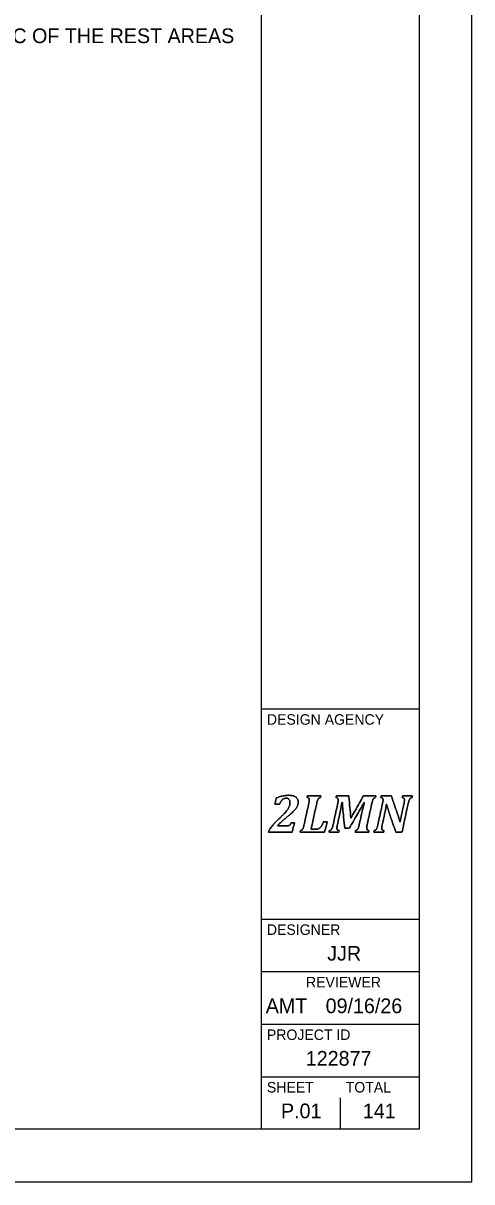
# Model space of a CAD drawing. Extents: x 0 to 34, y 0 to 22.
# Drawn here: x 29.73 to 34, y 0 to 11.03 of the extents above; entities that cross this region are included whole.
import ezdxf

# ---------------------------------------------------------------- set-up
doc = ezdxf.new("R2010")
doc.units = 0
for name, color, linetype in [('SH_Border', 7, 'Continuous'), ('SH_Cut_Line', 7, 'Continuous'), ('SH_Data', 7, 'Continuous')]:
    doc.layers.add(name, color=color, linetype=linetype)

msp = doc.modelspace()

# ---------------------------------------------------------------- linework, layer by layer
at = {"layer": 'SH_Border'}
for p, q in [((32, 0.5), (32, 21.5)), ((32, 4.5), (33.5, 4.5)), ((32, 2.5), (33.5, 2.5)), ((32, 2), (33.5, 2)), ((32, 1.5), (33.5, 1.5)), ((32, 1), (33.5, 1))]:
    msp.add_line(p, q, dxfattribs=at)
msp.add_lwpolyline([(1.5, 21.5), (33.5, 21.5), (33.5, 0.5), (1.5, 0.5)], close=True, dxfattribs=at)
at = {"layer": 'SH_Cut_Line'}
msp.add_lwpolyline([(0, 0), (34, 0), (34, 22), (0, 22)], close=True, dxfattribs=at)
at = {"layer": 'SH_Data'}
for p, q in [((32.75, 3.5), (32.75, 3.5)), ((32.75, 0.5), (32.75, 0.8)), ((32.375, 0.675), (32.375, 0.675))]:
    msp.add_line(p, q, dxfattribs=at)
for points in [[(32.237, 3.388), (32.246, 3.388), (32.253, 3.389), (32.258, 3.39), (32.263, 3.392), (32.267, 3.394), (32.27, 3.397), (32.273, 3.401), (32.277, 3.408), (32.281, 3.417), (32.281, 3.417), (32.312, 3.417), (32.312, 3.417), (32.312, 3.417), (32.29, 3.326), (32.29, 3.326), (32.29, 3.326), (32.066, 3.326), (32.066, 3.326), (32.066, 3.326), (32.069, 3.343), (32.069, 3.343), (32.078, 3.358), (32.091, 3.375), (32.106, 3.394), (32.122, 3.412), (32.144, 3.435), (32.172, 3.462), (32.197, 3.486), (32.217, 3.506), (32.23, 3.521), (32.243, 3.537), (32.253, 3.551), (32.259, 3.566), (32.266, 3.58), (32.269, 3.595), (32.269, 3.61), (32.269, 3.622), (32.266, 3.632), (32.26, 3.64), (32.253, 3.647), (32.245, 3.65), (32.234, 3.65), (32.22, 3.65), (32.208, 3.646), (32.198, 3.636), (32.188, 3.627), (32.18, 3.613), (32.172, 3.593), (32.172, 3.593), (32.126, 3.593), (32.126, 3.593), (32.126, 3.593), (32.14, 3.654), (32.14, 3.654), (32.166, 3.663), (32.188, 3.669), (32.205, 3.673), (32.223, 3.676), (32.24, 3.678), (32.258, 3.678), (32.278, 3.678), (32.295, 3.675), (32.309, 3.669), (32.322, 3.664), (32.332, 3.656), (32.339, 3.646), (32.345, 3.637), (32.348, 3.626), (32.348, 3.613), (32.348, 3.602), (32.346, 3.591), (32.342, 3.581), (32.339, 3.571), (32.333, 3.56), (32.324, 3.549), (32.315, 3.539), (32.304, 3.526), (32.289, 3.513), (32.275, 3.499), (32.254, 3.482), (32.228, 3.46), (32.216, 3.45), (32.202, 3.438), (32.188, 3.425), (32.174, 3.412), (32.162, 3.4), (32.154, 3.391), (32.154, 3.391), (32.153, 3.388), (32.153, 3.388), (32.153, 3.388), (32.237, 3.388), (32.237, 3.388)], [(32.237, 3.388), (32.237, 3.388), (32.153, 3.388), (32.153, 3.388), (32.153, 3.388), (32.154, 3.391), (32.154, 3.391), (32.162, 3.4), (32.174, 3.412), (32.188, 3.425), (32.202, 3.438), (32.216, 3.45), (32.228, 3.46), (32.254, 3.482), (32.275, 3.499), (32.289, 3.513), (32.304, 3.526), (32.315, 3.539), (32.324, 3.549), (32.333, 3.56), (32.339, 3.571), (32.342, 3.581), (32.346, 3.591), (32.348, 3.602), (32.348, 3.613), (32.348, 3.626), (32.345, 3.637), (32.339, 3.646), (32.332, 3.656), (32.322, 3.664), (32.309, 3.669), (32.295, 3.675), (32.278, 3.678), (32.258, 3.678), (32.24, 3.678), (32.223, 3.676), (32.205, 3.673), (32.188, 3.669), (32.166, 3.663), (32.14, 3.654), (32.14, 3.654), (32.126, 3.593), (32.126, 3.593), (32.126, 3.593), (32.172, 3.593), (32.172, 3.593), (32.18, 3.613), (32.188, 3.627), (32.198, 3.636), (32.208, 3.646), (32.22, 3.65), (32.234, 3.65), (32.245, 3.65), (32.253, 3.647), (32.26, 3.64), (32.266, 3.632), (32.269, 3.622), (32.269, 3.61), (32.269, 3.595), (32.266, 3.58), (32.259, 3.566), (32.253, 3.551), (32.243, 3.537), (32.23, 3.521), (32.217, 3.506), (32.197, 3.486), (32.172, 3.462), (32.144, 3.435), (32.122, 3.412), (32.106, 3.394), (32.091, 3.375), (32.078, 3.358), (32.069, 3.343), (32.069, 3.343), (32.066, 3.326), (32.066, 3.326), (32.066, 3.326), (32.29, 3.326), (32.29, 3.326), (32.29, 3.326), (32.312, 3.417), (32.312, 3.417), (32.312, 3.417), (32.281, 3.417), (32.281, 3.417), (32.277, 3.408), (32.273, 3.401), (32.27, 3.397), (32.267, 3.394), (32.263, 3.392), (32.258, 3.39), (32.253, 3.389), (32.246, 3.388), (32.237, 3.388)], [(32.518, 3.356), (32.527, 3.356), (32.533, 3.357), (32.538, 3.358), (32.542, 3.36), (32.546, 3.362), (32.55, 3.365), (32.554, 3.368), (32.558, 3.372), (32.562, 3.377), (32.567, 3.382), (32.571, 3.388), (32.576, 3.397), (32.58, 3.405), (32.585, 3.415), (32.589, 3.427), (32.589, 3.427), (32.624, 3.427), (32.624, 3.427), (32.624, 3.427), (32.598, 3.326), (32.598, 3.326), (32.598, 3.326), (32.365, 3.326), (32.365, 3.326), (32.365, 3.326), (32.369, 3.343), (32.369, 3.343), (32.376, 3.345), (32.381, 3.348), (32.385, 3.351), (32.389, 3.355), (32.392, 3.36), (32.395, 3.366), (32.398, 3.373), (32.4, 3.382), (32.403, 3.395), (32.403, 3.395), (32.449, 3.605), (32.449, 3.605), (32.452, 3.615), (32.453, 3.625), (32.453, 3.635), (32.453, 3.642), (32.451, 3.647), (32.448, 3.651), (32.444, 3.654), (32.439, 3.656), (32.432, 3.657), (32.432, 3.657), (32.435, 3.674), (32.435, 3.674), (32.435, 3.674), (32.563, 3.674), (32.563, 3.674), (32.563, 3.674), (32.559, 3.657), (32.559, 3.657), (32.552, 3.655), (32.547, 3.652), (32.543, 3.649), (32.539, 3.645), (32.536, 3.64), (32.533, 3.634), (32.531, 3.627), (32.528, 3.618), (32.525, 3.605), (32.525, 3.605), (32.47, 3.356), (32.47, 3.356), (32.47, 3.356), (32.518, 3.356), (32.518, 3.356)], [(32.518, 3.356), (32.518, 3.356), (32.47, 3.356), (32.47, 3.356), (32.47, 3.356), (32.525, 3.605), (32.525, 3.605), (32.528, 3.618), (32.531, 3.627), (32.533, 3.634), (32.536, 3.64), (32.539, 3.645), (32.543, 3.649), (32.547, 3.652), (32.552, 3.655), (32.559, 3.657), (32.559, 3.657), (32.563, 3.674), (32.563, 3.674), (32.563, 3.674), (32.435, 3.674), (32.435, 3.674), (32.435, 3.674), (32.432, 3.657), (32.432, 3.657), (32.439, 3.656), (32.444, 3.654), (32.448, 3.651), (32.451, 3.647), (32.453, 3.642), (32.453, 3.635), (32.453, 3.625), (32.452, 3.615), (32.449, 3.605), (32.449, 3.605), (32.403, 3.395), (32.403, 3.395), (32.4, 3.382), (32.398, 3.373), (32.395, 3.366), (32.392, 3.36), (32.389, 3.355), (32.385, 3.351), (32.381, 3.348), (32.376, 3.345), (32.369, 3.343), (32.369, 3.343), (32.365, 3.326), (32.365, 3.326), (32.365, 3.326), (32.598, 3.326), (32.598, 3.326), (32.598, 3.326), (32.624, 3.427), (32.624, 3.427), (32.624, 3.427), (32.589, 3.427), (32.589, 3.427), (32.585, 3.415), (32.58, 3.405), (32.576, 3.397), (32.571, 3.388), (32.567, 3.382), (32.562, 3.377), (32.558, 3.372), (32.554, 3.368), (32.55, 3.365), (32.546, 3.362), (32.542, 3.36), (32.538, 3.358), (32.533, 3.357), (32.527, 3.356), (32.518, 3.356)], [(32.829, 3.674), (32.829, 3.674), (32.849, 3.461), (32.849, 3.461), (32.849, 3.461), (32.969, 3.674), (32.969, 3.674), (32.969, 3.674), (33.087, 3.674), (33.087, 3.674), (33.087, 3.674), (33.084, 3.657), (33.084, 3.657), (33.077, 3.655), (33.071, 3.652), (33.067, 3.649), (33.064, 3.645), (33.06, 3.64), (33.058, 3.634), (33.055, 3.627), (33.052, 3.618), (33.05, 3.605), (33.05, 3.605), (33.003, 3.395), (33.003, 3.395), (33.002, 3.39), (33.002, 3.387), (33.001, 3.384), (33.001, 3.382), (33.001, 3.379), (33, 3.376), (33, 3.373), (33, 3.369), (33, 3.365), (33, 3.358), (33.002, 3.353), (33.005, 3.349), (33.008, 3.346), (33.014, 3.344), (33.021, 3.343), (33.021, 3.343), (33.018, 3.326), (33.018, 3.326), (33.018, 3.326), (32.89, 3.326), (32.89, 3.326), (32.89, 3.326), (32.893, 3.343), (32.893, 3.343), (32.9, 3.345), (32.906, 3.348), (32.91, 3.351), (32.914, 3.355), (32.917, 3.36), (32.919, 3.366), (32.922, 3.373), (32.925, 3.382), (32.928, 3.395), (32.928, 3.395), (32.951, 3.502), (32.951, 3.502), (32.954, 3.513), (32.957, 3.529), (32.962, 3.548), (32.967, 3.568), (32.972, 3.588), (32.978, 3.609), (32.978, 3.609), (32.973, 3.609), (32.973, 3.609), (32.965, 3.594), (32.957, 3.579), (32.948, 3.563), (32.948, 3.563), (32.833, 3.364), (32.833, 3.364), (32.833, 3.364), (32.792, 3.364), (32.792, 3.364), (32.792, 3.364), (32.775, 3.518), (32.775, 3.518), (32.773, 3.537), (32.772, 3.554), (32.77, 3.569), (32.769, 3.583), (32.768, 3.597), (32.768, 3.611), (32.768, 3.611), (32.764, 3.611), (32.764, 3.611), (32.761, 3.596), (32.758, 3.578), (32.755, 3.558), (32.751, 3.538), (32.747, 3.521), (32.744, 3.507), (32.744, 3.507), (32.72, 3.395), (32.72, 3.395), (32.719, 3.39), (32.718, 3.387), (32.718, 3.384), (32.717, 3.382), (32.717, 3.379), (32.717, 3.376), (32.717, 3.373), (32.716, 3.369), (32.716, 3.365), (32.716, 3.358), (32.718, 3.353), (32.721, 3.349), (32.725, 3.346), (32.73, 3.344), (32.738, 3.343), (32.738, 3.343), (32.734, 3.326), (32.734, 3.326), (32.734, 3.326), (32.641, 3.326), (32.641, 3.326), (32.641, 3.326), (32.644, 3.343), (32.644, 3.343), (32.651, 3.345), (32.657, 3.348), (32.661, 3.351), (32.665, 3.355), (32.668, 3.36), (32.67, 3.366), (32.673, 3.373), (32.676, 3.382), (32.679, 3.395), (32.679, 3.395), (32.725, 3.605), (32.725, 3.605), (32.727, 3.615), (32.728, 3.625), (32.728, 3.635), (32.728, 3.642), (32.727, 3.647), (32.723, 3.651), (32.72, 3.654), (32.715, 3.656), (32.707, 3.657), (32.707, 3.657), (32.711, 3.674), (32.711, 3.674), (32.711, 3.674), (32.829, 3.674), (32.829, 3.674)], [(32.829, 3.674), (32.829, 3.674), (32.711, 3.674), (32.711, 3.674), (32.711, 3.674), (32.707, 3.657), (32.707, 3.657), (32.715, 3.656), (32.72, 3.654), (32.723, 3.651), (32.727, 3.647), (32.728, 3.642), (32.728, 3.635), (32.728, 3.625), (32.727, 3.615), (32.725, 3.605), (32.725, 3.605), (32.679, 3.395), (32.679, 3.395), (32.676, 3.382), (32.673, 3.373), (32.67, 3.366), (32.668, 3.36), (32.665, 3.355), (32.661, 3.351), (32.657, 3.348), (32.651, 3.345), (32.644, 3.343), (32.644, 3.343), (32.641, 3.326), (32.641, 3.326), (32.641, 3.326), (32.734, 3.326), (32.734, 3.326), (32.734, 3.326), (32.738, 3.343), (32.738, 3.343), (32.73, 3.344), (32.725, 3.346), (32.721, 3.349), (32.718, 3.353), (32.716, 3.358), (32.716, 3.365), (32.716, 3.369), (32.717, 3.373), (32.717, 3.376), (32.717, 3.379), (32.717, 3.382), (32.718, 3.384), (32.718, 3.387), (32.719, 3.39), (32.72, 3.395), (32.72, 3.395), (32.744, 3.507), (32.744, 3.507), (32.747, 3.521), (32.751, 3.538), (32.755, 3.558), (32.758, 3.578), (32.761, 3.596), (32.764, 3.611), (32.764, 3.611), (32.768, 3.611), (32.768, 3.611), (32.768, 3.597), (32.769, 3.583), (32.77, 3.569), (32.772, 3.554), (32.773, 3.537), (32.775, 3.518), (32.775, 3.518), (32.792, 3.364), (32.792, 3.364), (32.792, 3.364), (32.833, 3.364), (32.833, 3.364), (32.833, 3.364), (32.948, 3.563), (32.948, 3.563), (32.957, 3.579), (32.965, 3.594), (32.973, 3.609), (32.973, 3.609), (32.978, 3.609), (32.978, 3.609), (32.972, 3.588), (32.967, 3.568), (32.962, 3.548), (32.957, 3.529), (32.954, 3.513), (32.951, 3.502), (32.951, 3.502), (32.928, 3.395), (32.928, 3.395), (32.925, 3.382), (32.922, 3.373), (32.919, 3.366), (32.917, 3.36), (32.914, 3.355), (32.91, 3.351), (32.906, 3.348), (32.9, 3.345), (32.893, 3.343), (32.893, 3.343), (32.89, 3.326), (32.89, 3.326), (32.89, 3.326), (33.018, 3.326), (33.018, 3.326), (33.018, 3.326), (33.021, 3.343), (33.021, 3.343), (33.014, 3.344), (33.008, 3.346), (33.005, 3.349), (33.002, 3.353), (33, 3.358), (33, 3.365), (33, 3.369), (33, 3.373), (33, 3.376), (33.001, 3.379), (33.001, 3.382), (33.001, 3.384), (33.002, 3.387), (33.002, 3.39), (33.003, 3.395), (33.003, 3.395), (33.05, 3.605), (33.05, 3.605), (33.052, 3.618), (33.055, 3.627), (33.058, 3.634), (33.06, 3.64), (33.064, 3.645), (33.067, 3.649), (33.071, 3.652), (33.077, 3.655), (33.084, 3.657), (33.084, 3.657), (33.087, 3.674), (33.087, 3.674), (33.087, 3.674), (32.969, 3.674), (32.969, 3.674), (32.969, 3.674), (32.849, 3.461), (32.849, 3.461), (32.849, 3.461), (32.829, 3.674), (32.829, 3.674)], [(33.137, 3.674), (33.137, 3.674), (33.234, 3.674), (33.234, 3.674), (33.234, 3.674), (33.283, 3.53), (33.283, 3.53), (33.296, 3.49), (33.307, 3.456), (33.315, 3.426), (33.315, 3.426), (33.318, 3.426), (33.318, 3.426), (33.323, 3.455), (33.329, 3.488), (33.337, 3.523), (33.337, 3.523), (33.355, 3.605), (33.355, 3.605), (33.357, 3.615), (33.358, 3.625), (33.358, 3.635), (33.358, 3.642), (33.357, 3.647), (33.353, 3.651), (33.35, 3.654), (33.345, 3.656), (33.337, 3.657), (33.337, 3.657), (33.341, 3.674), (33.341, 3.674), (33.341, 3.674), (33.434, 3.674), (33.434, 3.674), (33.434, 3.674), (33.431, 3.657), (33.431, 3.657), (33.424, 3.655), (33.418, 3.652), (33.414, 3.649), (33.41, 3.645), (33.407, 3.64), (33.405, 3.634), (33.402, 3.627), (33.399, 3.618), (33.396, 3.605), (33.396, 3.605), (33.335, 3.326), (33.335, 3.326), (33.335, 3.326), (33.277, 3.326), (33.277, 3.326), (33.277, 3.326), (33.216, 3.504), (33.216, 3.504), (33.211, 3.518), (33.207, 3.531), (33.204, 3.543), (33.2, 3.556), (33.195, 3.571), (33.19, 3.59), (33.19, 3.59), (33.186, 3.59), (33.186, 3.59), (33.185, 3.579), (33.182, 3.563), (33.179, 3.543), (33.175, 3.523), (33.17, 3.501), (33.165, 3.478), (33.165, 3.478), (33.147, 3.395), (33.147, 3.395), (33.146, 3.39), (33.145, 3.387), (33.145, 3.384), (33.144, 3.382), (33.144, 3.379), (33.144, 3.376), (33.143, 3.373), (33.143, 3.369), (33.143, 3.365), (33.143, 3.358), (33.145, 3.353), (33.148, 3.349), (33.152, 3.346), (33.157, 3.344), (33.164, 3.343), (33.164, 3.343), (33.161, 3.326), (33.161, 3.326), (33.161, 3.326), (33.067, 3.326), (33.067, 3.326), (33.067, 3.326), (33.071, 3.343), (33.071, 3.343), (33.078, 3.345), (33.083, 3.348), (33.087, 3.351), (33.091, 3.355), (33.094, 3.36), (33.097, 3.366), (33.1, 3.373), (33.102, 3.382), (33.105, 3.395), (33.105, 3.395), (33.151, 3.605), (33.151, 3.605), (33.154, 3.615), (33.155, 3.625), (33.155, 3.635), (33.155, 3.642), (33.153, 3.647), (33.15, 3.651), (33.146, 3.654), (33.141, 3.656), (33.134, 3.657), (33.134, 3.657), (33.137, 3.674), (33.137, 3.674)], [(33.137, 3.674), (33.137, 3.674), (33.134, 3.657), (33.134, 3.657), (33.141, 3.656), (33.146, 3.654), (33.15, 3.651), (33.153, 3.647), (33.155, 3.642), (33.155, 3.635), (33.155, 3.625), (33.154, 3.615), (33.151, 3.605), (33.151, 3.605), (33.105, 3.395), (33.105, 3.395), (33.102, 3.382), (33.1, 3.373), (33.097, 3.366), (33.094, 3.36), (33.091, 3.355), (33.087, 3.351), (33.083, 3.348), (33.078, 3.345), (33.071, 3.343), (33.071, 3.343), (33.067, 3.326), (33.067, 3.326), (33.067, 3.326), (33.161, 3.326), (33.161, 3.326), (33.161, 3.326), (33.164, 3.343), (33.164, 3.343), (33.157, 3.344), (33.152, 3.346), (33.148, 3.349), (33.145, 3.353), (33.143, 3.358), (33.143, 3.365), (33.143, 3.369), (33.143, 3.373), (33.144, 3.376), (33.144, 3.379), (33.144, 3.382), (33.145, 3.384), (33.145, 3.387), (33.146, 3.39), (33.147, 3.395), (33.147, 3.395), (33.165, 3.478), (33.165, 3.478), (33.17, 3.501), (33.175, 3.523), (33.179, 3.543), (33.182, 3.563), (33.185, 3.579), (33.186, 3.59), (33.186, 3.59), (33.19, 3.59), (33.19, 3.59), (33.195, 3.571), (33.2, 3.556), (33.204, 3.543), (33.207, 3.531), (33.211, 3.518), (33.216, 3.504), (33.216, 3.504), (33.277, 3.326), (33.277, 3.326), (33.277, 3.326), (33.335, 3.326), (33.335, 3.326), (33.335, 3.326), (33.396, 3.605), (33.396, 3.605), (33.399, 3.618), (33.402, 3.627), (33.405, 3.634), (33.407, 3.64), (33.41, 3.645), (33.414, 3.649), (33.418, 3.652), (33.424, 3.655), (33.431, 3.657), (33.431, 3.657), (33.434, 3.674), (33.434, 3.674), (33.434, 3.674), (33.341, 3.674), (33.341, 3.674), (33.341, 3.674), (33.337, 3.657), (33.337, 3.657), (33.345, 3.656), (33.35, 3.654), (33.353, 3.651), (33.357, 3.647), (33.358, 3.642), (33.358, 3.635), (33.358, 3.625), (33.357, 3.615), (33.355, 3.605), (33.355, 3.605), (33.337, 3.523), (33.337, 3.523), (33.329, 3.488), (33.323, 3.455), (33.318, 3.426), (33.318, 3.426), (33.315, 3.426), (33.315, 3.426), (33.307, 3.456), (33.296, 3.49), (33.283, 3.53), (33.283, 3.53), (33.234, 3.674), (33.234, 3.674), (33.234, 3.674), (33.137, 3.674), (33.137, 3.674)]]:
    msp.add_open_spline(points, degree=3, dxfattribs=at)

# ---------------------------------------------------------------- texts
for s, height, p in [('IMPROVEMENT WILL REQUIRE THE CLOSING TO TRAFFIC OF THE REST AREAS', 0.14, (24.5, 10.836)), ('DESIGN AGENCY', 0.1, (32.05, 4.35)), ('DESIGNER', 0.1, (32.05, 2.35)), ('JJR', 0.14, (32.624, 2.105)), ('REVIEWER', 0.1, (32.422, 1.85)), ('AMT', 0.14, (32.039, 1.605)), ('09/16/26', 0.14, (32.609, 1.605)), ('PROJECT ID', 0.1, (32.05, 1.35)), ('122877', 0.14, (32.42, 1.105)), ('SHEET', 0.1, (32.05, 0.85)), ('TOTAL', 0.1, (32.8, 0.85)), ('P.01', 0.14, (32.184, 0.605)), ('141', 0.14, (32.963, 0.605))]:
    msp.add_text(s, height=height, dxfattribs=at).set_placement(p)

doc.saveas('drawing.dxf')
